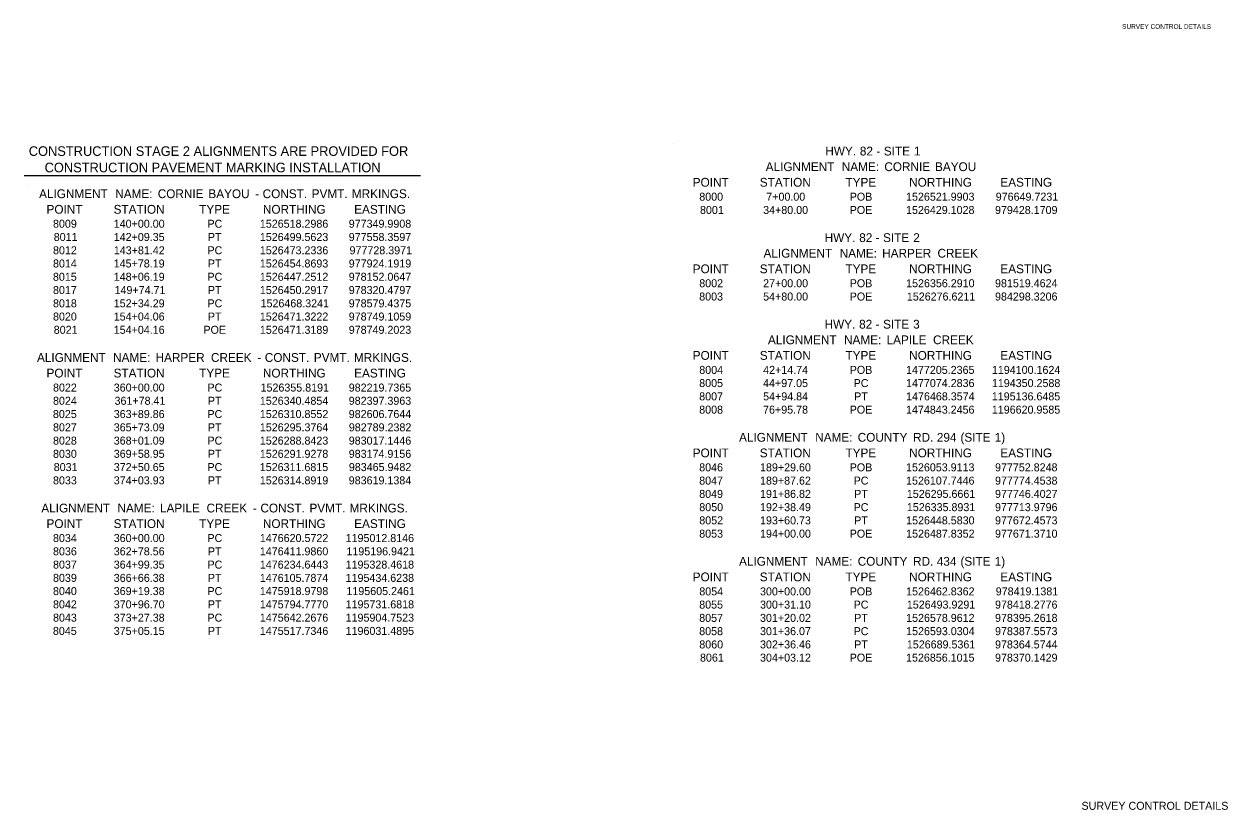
# Model space of a CAD drawing. Extents: x 977669 to 1196358, y 1472413 to 1526490.
# Drawn here: x 1194854 to 1196358, y 1472413 to 1473395 of the extents above; entities that cross this region are included whole.
import ezdxf

# ---------------------------------------------------------------- set-up
doc = ezdxf.new("R2010")
doc.units = 0
for name, color, linetype in [('Default', 7, 'Continuous'), ('R_Annotation', 7, 'Continuous'), ('R_Border', 7, 'Continuous')]:
    doc.layers.add(name, color=color, linetype=linetype)

msp = doc.modelspace()

# ---------------------------------------------------------------- linework, layer by layer
at = {"layer": 'Default'}
msp.add_line((1194853.8, 1473205.4), (1195349.1, 1473205.4), dxfattribs=at)
at = {"layer": 'R_Border'}
for p, q in [((1195666.1, 1473245.9), (1195666.1, 1473245.9)), ((1194858.4, 1473192.6), (1194858.4, 1473192.6))]:
    msp.add_line(p, q, dxfattribs=at)

# ---------------------------------------------------------------- texts
at = {"layer": 'Default'}
for s, height, p in [('CONSTRUCTION STAGE 2 ALIGNMENTS ARE PROVIDED FOR', 12, (1194859.7, 1473230.1)), ('HWY.', 11, (1195855.2, 1473230.6)), (' 82', 11, (1195894.3, 1473230.6)), (' SITE', 11, (1195924.2, 1473230.6)), (' 1', 11, (1195961.8, 1473230.6)), (' -', 11, (1195914.9, 1473230.6)), ('CONSTRUCTION PAVEMENT MARKING INSTALLATION', 12, (1194879.5, 1473209.6)), ('ALIGNMENT', 11, (1195780.7, 1473211.1)), (' NAME:', 11, (1195871.7, 1473211.1)), (' CORNIE', 11, (1195924.9, 1473211.1)), (' BAYOU', 11, (1195988.2, 1473211.1)), ('POINT', 11, (1195689.5, 1473191.6)), ('STATION', 11, (1195773.3, 1473191.6)), ('TYPE', 11, (1195880.4, 1473191.6)), ('NORTHING', 11, (1195960, 1473191.6)), ('EASTING', 11, (1196074, 1473191.6)), ('ALIGNMENT', 11, (1194872.6, 1473177.3)), (' NAME:', 11, (1194963.7, 1473177.3)), (' CORNIE', 11, (1195016.8, 1473177.3)), (' BAYOU', 11, (1195080.1, 1473177.3)), (' -', 11, (1195138.6, 1473177.3)), (' CONST.', 11, (1195147.9, 1473177.3)), (' PVMT.', 11, (1195209.2, 1473177.3)), (' MRKINGS.', 11, (1195259.4, 1473177.3)), ('8000', 10, (1195697.7, 1473174.1)), ('7+00.00', 10, (1195781.4, 1473174.1)), ('POB', 10, (1195885.7, 1473174.1)), ('1526521.9903', 10, (1195956.1, 1473174.1)), ('976649.7231', 10, (1196068.2, 1473174.1)), ('POINT', 11, (1194881.9, 1473157.8)), ('STATION', 11, (1194965.7, 1473157.8)), ('TYPE', 11, (1195072.7, 1473157.8)), ('NORTHING', 11, (1195152.3, 1473157.8)), ('EASTING', 11, (1195266.4, 1473157.8)), ('8001', 10, (1195698.6, 1473157.5)), ('34+80.00', 10, (1195777.5, 1473157.5)), ('POE', 10, (1195885.7, 1473157.5)), ('1526429.1028', 10, (1195956.1, 1473157.5)), ('979428.1709', 10, (1196067.3, 1473157.5)), ('8009', 10, (1194890, 1473140.3)), ('140+00.00', 10, (1194965.9, 1473140.3)), ('PC', 10, (1195083, 1473140.3)), ('1526518.2986', 10, (1195148.5, 1473140.3)), ('977349.9908', 10, (1195259.6, 1473140.3)), ('8011', 10, (1194890.9, 1473123.7)), ('142+09.35', 10, (1194965.9, 1473123.7)), ('PT', 10, (1195083.6, 1473123.7)), ('1526499.5623', 10, (1195148.5, 1473123.7)), ('977558.3597', 10, (1195259.6, 1473123.7)), (' 82', 11, (1195893.5, 1473122.4)), (' SITE', 11, (1195923.3, 1473122.4)), (' 2', 11, (1195961, 1473122.4)), ('HWY.', 11, (1195854.4, 1473122.4)), (' -', 11, (1195914, 1473122.4)), ('8012', 10, (1194890, 1473107.1)), ('143+81.42', 10, (1194966, 1473107.1)), ('PC', 10, (1195083, 1473107.1)), ('1526473.2336', 10, (1195148.5, 1473107.1)), ('977728.3971', 10, (1195260.6, 1473107.1)), ('ALIGNMENT', 11, (1195778, 1473102.9)), (' NAME:', 11, (1195869.1, 1473102.9)), (' HARPER', 11, (1195922.2, 1473102.9)), (' CREEK', 11, (1195991.3, 1473102.9)), ('8014', 10, (1194890, 1473090.6)), ('145+78.19', 10, (1194965.9, 1473090.6)), ('PT', 10, (1195083.6, 1473090.6)), ('1526454.8693', 10, (1195148.5, 1473090.6)), ('977924.1919', 10, (1195259.6, 1473090.6)), ('POINT', 11, (1195689.5, 1473083.4)), ('STATION', 11, (1195773.3, 1473083.4)), ('TYPE', 11, (1195880.4, 1473083.4)), ('NORTHING', 11, (1195960, 1473083.4)), ('EASTING', 11, (1196074, 1473083.4)), ('8015', 10, (1194889.9, 1473074)), ('148+06.19', 10, (1194965.9, 1473074)), ('PC', 10, (1195083, 1473074)), ('1526447.2512', 10, (1195148.5, 1473074)), ('978152.0647', 10, (1195259.6, 1473074)), ('8002', 10, (1195697.7, 1473065.9)), ('27+00.00', 10, (1195777.5, 1473065.9)), ('POB', 10, (1195885.7, 1473065.9)), ('1526356.2910', 10, (1195956.2, 1473065.9)), ('981519.4624', 10, (1196067.3, 1473065.9)), ('8017', 10, (1194890, 1473057.4)), ('149+74.71', 10, (1194966.9, 1473057.4)), ('PT', 10, (1195083.6, 1473057.4)), ('1526450.2917', 10, (1195148.5, 1473057.4)), ('978320.4797', 10, (1195259.6, 1473057.4)), ('8003', 10, (1195697.6, 1473049.3)), ('54+80.00', 10, (1195777.5, 1473049.3)), ('POE', 10, (1195885.7, 1473049.3)), ('1526276.6211', 10, (1195957.1, 1473049.3)), ('984298.3206', 10, (1196067.3, 1473049.3)), ('8018', 10, (1194890, 1473040.8)), ('152+34.29', 10, (1194965.9, 1473040.8)), ('PC', 10, (1195083, 1473040.8)), ('1526468.3241', 10, (1195149.4, 1473040.8)), ('978579.4375', 10, (1195259.6, 1473040.8)), ('8020', 10, (1194890, 1473024.3)), ('154+04.06', 10, (1194965.9, 1473024.3)), ('PT', 10, (1195083.6, 1473024.3)), ('1526471.3222', 10, (1195148.5, 1473024.3)), ('978749.1059', 10, (1195259.6, 1473024.3)), ('8021', 10, (1194890.9, 1473007.7)), ('154+04.16', 10, (1194965.9, 1473007.7)), ('POE', 10, (1195078, 1473007.7)), ('1526471.3189', 10, (1195148.5, 1473007.7)), ('978749.2023', 10, (1195259.6, 1473007.7)), ('HWY.', 11, (1195854.3, 1473014.2)), (' 82', 11, (1195893.4, 1473014.2)), (' -', 11, (1195914, 1473014.2)), (' SITE', 11, (1195923.3, 1473014.2)), (' 3', 11, (1195960.9, 1473014.2)), ('ALIGNMENT', 11, (1195783.5, 1472994.7)), (' NAME:', 11, (1195874.5, 1472994.7)), (' LAPILE', 11, (1195927.7, 1472994.7)), (' CREEK', 11, (1195985.8, 1472994.7)), ('ALIGNMENT', 11, (1194870, 1472972.6)), (' NAME:', 11, (1194961, 1472972.6)), (' HARPER', 11, (1195014.1, 1472972.6)), (' CREEK', 11, (1195083.3, 1472972.6)), (' CONST.', 11, (1195150.6, 1472972.6)), (' PVMT.', 11, (1195211.9, 1472972.6)), (' MRKINGS.', 11, (1195262, 1472972.6)), ('POINT', 11, (1195689.5, 1472975.2)), ('STATION', 11, (1195773.3, 1472975.2)), ('TYPE', 11, (1195880.4, 1472975.2)), ('NORTHING', 11, (1195960, 1472975.2)), ('EASTING', 11, (1196074, 1472975.2)), (' -', 11, (1195141.3, 1472972.6)), ('POINT', 11, (1194881.9, 1472953.1)), ('STATION', 11, (1194965.7, 1472953.1)), ('TYPE', 11, (1195072.7, 1472953.1)), ('NORTHING', 11, (1195152.3, 1472953.1)), ('EASTING', 11, (1195266.4, 1472953.1)), ('8004', 10, (1195697.7, 1472957.6)), ('42+14.74', 10, (1195777.5, 1472957.6)), ('POB', 10, (1195885.7, 1472957.6)), ('1477205.2365', 10, (1195956.1, 1472957.6)), ('1194100.1624', 10, (1196063.4, 1472957.6)), ('8022', 10, (1194890, 1472935.5)), ('360+00.00', 10, (1194965.9, 1472935.5)), ('PC', 10, (1195083, 1472935.5)), ('1526355.8191', 10, (1195149.4, 1472935.5)), ('982219.7365', 10, (1195259.6, 1472935.5)), ('8005', 10, (1195697.6, 1472941.1)), ('44+97.05', 10, (1195777.4, 1472941.1)), ('PC', 10, (1195890.6, 1472941.1)), ('1477074.2836', 10, (1195956.1, 1472941.1)), ('1194350.2588', 10, (1196063.4, 1472941.1)), ('8024', 10, (1194890, 1472919)), ('361+78.41', 10, (1194966.9, 1472919)), ('PT', 10, (1195083.6, 1472919)), ('1526340.4854', 10, (1195148.5, 1472919)), ('982397.3963', 10, (1195259.6, 1472919)), ('8007', 10, (1195697.6, 1472924.5)), ('54+94.84', 10, (1195777.5, 1472924.5)), ('PT', 10, (1195891.3, 1472924.5)), ('1476468.3574', 10, (1195956.2, 1472924.5)), ('1195136.6485', 10, (1196063.3, 1472924.5)), ('8025', 10, (1194889.9, 1472902.4)), ('363+89.86', 10, (1194965.9, 1472902.4)), ('PC', 10, (1195083, 1472902.4)), ('1526310.8552', 10, (1195148.5, 1472902.4)), ('982606.7644', 10, (1195259.6, 1472902.4)), ('8008', 10, (1195697.6, 1472907.9)), ('76+95.78', 10, (1195777.4, 1472907.9)), ('POE', 10, (1195885.7, 1472907.9)), ('1474843.2456', 10, (1195956.1, 1472907.9)), ('1196620.9585', 10, (1196063.3, 1472907.9)), ('8027', 10, (1194890, 1472885.8)), ('365+73.09', 10, (1194965.9, 1472885.8)), ('PT', 10, (1195083.6, 1472885.8)), ('1526295.3764', 10, (1195148.5, 1472885.8)), ('982789.2382', 10, (1195259.7, 1472885.8)), ('8028', 10, (1194890, 1472869.2)), ('368+01.09', 10, (1194965.9, 1472869.2)), ('PC', 10, (1195083, 1472869.2)), ('1526288.8423', 10, (1195148.5, 1472869.2)), ('983017.1446', 10, (1195259.6, 1472869.2)), ('ALIGNMENT', 11, (1195747.4, 1472872.8)), (' NAME:', 11, (1195838.5, 1472872.8)), (' COUNTY', 11, (1195891.6, 1472872.8)), (' RD.', 11, (1195960.8, 1472872.8)), (' 294', 11, (1195990.5, 1472872.8)), (' (SITE', 11, (1196020, 1472872.8)), (' 1)', 11, (1196062.8, 1472872.8)), ('8030', 10, (1194890, 1472852.7)), ('369+58.95', 10, (1194965.9, 1472852.7)), ('1526291.9278', 10, (1195148.5, 1472852.7)), ('983174.9156', 10, (1195259.6, 1472852.7)), ('POINT', 11, (1195689.5, 1472853.3)), ('STATION', 11, (1195773.3, 1472853.3)), ('TYPE', 11, (1195880.4, 1472853.3)), ('NORTHING', 11, (1195960, 1472853.3)), ('EASTING', 11, (1196074, 1472853.3)), ('PT', 10, (1195083.6, 1472852.7)), ('8031', 10, (1194890.9, 1472836.1)), ('372+50.65', 10, (1194965.9, 1472836.1)), ('PC', 10, (1195083, 1472836.1)), ('1526311.6815', 10, (1195148.4, 1472836.1)), ('983465.9482', 10, (1195259.7, 1472836.1)), ('8046', 10, (1195697.6, 1472835.8)), ('189+29.60', 10, (1195773.6, 1472835.8)), ('POB', 10, (1195885.7, 1472835.8)), ('1526053.9113', 10, (1195956.1, 1472835.8)), ('977752.8248', 10, (1196067.3, 1472835.8)), ('8033', 10, (1194890, 1472819.5)), ('374+03.93', 10, (1194965.9, 1472819.5)), ('PT', 10, (1195083.6, 1472819.5)), ('1526314.8919', 10, (1195148.5, 1472819.5)), ('983619.1384', 10, (1195259.6, 1472819.5)), ('8047', 10, (1195697.6, 1472819.2)), ('189+87.62', 10, (1195773.6, 1472819.2)), ('PC', 10, (1195890.6, 1472819.2)), ('1526107.7446', 10, (1195956.1, 1472819.2)), ('977774.4538', 10, (1196067.3, 1472819.2)), ('8049', 10, (1195697.6, 1472802.6)), ('191+86.82', 10, (1195773.6, 1472802.6)), ('PT', 10, (1195891.3, 1472802.6)), ('1526295.6661', 10, (1195957.1, 1472802.6)), ('977746.4027', 10, (1196067.3, 1472802.6)), ('ALIGNMENT', 11, (1194875.4, 1472784.4)), (' NAME:', 11, (1194966.5, 1472784.4)), (' LAPILE', 11, (1195019.6, 1472784.4)), (' CREEK', 11, (1195077.8, 1472784.4)), (' -', 11, (1195135.8, 1472784.4)), (' CONST.', 11, (1195145.1, 1472784.4)), (' PVMT.', 11, (1195206.4, 1472784.4)), (' MRKINGS.', 11, (1195256.6, 1472784.4)), ('8050', 10, (1195697.7, 1472786)), ('192+38.49', 10, (1195773.6, 1472786)), ('PC', 10, (1195890.6, 1472786)), ('1526335.8931', 10, (1195957.1, 1472786)), ('977713.9796', 10, (1196067.3, 1472786)), ('POINT', 11, (1194881.9, 1472764.9)), ('STATION', 11, (1194965.7, 1472764.9)), ('TYPE', 11, (1195072.7, 1472764.9)), ('NORTHING', 11, (1195152.3, 1472764.9)), ('EASTING', 11, (1195266.4, 1472764.9)), ('8052', 10, (1195697.7, 1472769.5)), ('193+60.73', 10, (1195773.6, 1472769.5)), ('PT', 10, (1195891.3, 1472769.5)), ('1526448.5830', 10, (1195956.2, 1472769.5)), ('977672.4573', 10, (1196067.3, 1472769.5)), ('8034', 10, (1194890, 1472747.4)), ('360+00.00', 10, (1194965.9, 1472747.4)), ('PC', 10, (1195083, 1472747.4)), ('1476620.5722', 10, (1195148.5, 1472747.4)), ('1195012.8146', 10, (1195255.7, 1472747.4)), ('8053', 10, (1195697.6, 1472752.9)), ('194+00.00', 10, (1195773.6, 1472752.9)), ('POE', 10, (1195885.7, 1472752.9)), ('1526487.8352', 10, (1195956.2, 1472752.9)), ('977671.3710', 10, (1196067.3, 1472752.9)), ('8036', 10, (1194890, 1472730.8)), ('362+78.56', 10, (1194965.9, 1472730.8)), ('PT', 10, (1195083.6, 1472730.8)), ('1476411.9860', 10, (1195148.5, 1472730.8)), ('1195196.9421', 10, (1195256.7, 1472730.8)), ('ALIGNMENT', 11, (1195747.4, 1472717.8)), (' NAME:', 11, (1195838.5, 1472717.8)), (' COUNTY', 11, (1195891.6, 1472717.8)), (' RD.', 11, (1195960.8, 1472717.8)), (' 434', 11, (1195990.5, 1472717.8)), (' (SITE', 11, (1196020, 1472717.8)), (' 1)', 11, (1196062.8, 1472717.8)), ('8037', 10, (1194890, 1472714.2)), ('364+99.35', 10, (1194965.9, 1472714.2)), ('PC', 10, (1195083, 1472714.2)), ('1476234.6443', 10, (1195148.5, 1472714.2)), ('1195328.4618', 10, (1195255.7, 1472714.2)), ('8039', 10, (1194890, 1472697.6)), ('366+66.38', 10, (1194965.9, 1472697.6)), ('PT', 10, (1195083.6, 1472697.6)), ('1476105.7874', 10, (1195148.5, 1472697.6)), ('1195434.6238', 10, (1195255.7, 1472697.6)), ('POINT', 11, (1195689.5, 1472698.3)), ('STATION', 11, (1195773.3, 1472698.3)), ('TYPE', 11, (1195880.4, 1472698.3)), ('NORTHING', 11, (1195960, 1472698.3)), ('EASTING', 11, (1196074, 1472698.3)), ('8040', 10, (1194890, 1472681.1)), ('369+19.38', 10, (1194965.9, 1472681.1)), ('PC', 10, (1195083, 1472681.1)), ('1475918.9798', 10, (1195148.5, 1472681.1)), ('1195605.2461', 10, (1195256.7, 1472681.1)), ('8054', 10, (1195697.7, 1472680.7)), ('300+00.00', 10, (1195773.6, 1472680.7)), ('POB', 10, (1195885.7, 1472680.7)), ('1526462.8362', 10, (1195956.2, 1472680.7)), ('978419.1381', 10, (1196068.2, 1472680.7)), ('8042', 10, (1194890, 1472664.5)), ('370+96.70', 10, (1194965.9, 1472664.5)), ('PT', 10, (1195083.6, 1472664.5)), ('1475794.7770', 10, (1195148.5, 1472664.5)), ('1195731.6818', 10, (1195255.7, 1472664.5)), ('8055', 10, (1195697.6, 1472664.2)), ('300+31.10', 10, (1195773.6, 1472664.2)), ('PC', 10, (1195890.6, 1472664.2)), ('1526493.9291', 10, (1195957.1, 1472664.2)), ('978418.2776', 10, (1196067.3, 1472664.2)), ('8043', 10, (1194890, 1472647.9)), ('373+27.38', 10, (1194965.9, 1472647.9)), ('PC', 10, (1195083, 1472647.9)), ('1475642.2676', 10, (1195148.5, 1472647.9)), ('1195904.7523', 10, (1195255.7, 1472647.9)), ('8057', 10, (1195697.6, 1472647.6)), ('301+20.02', 10, (1195773.6, 1472647.6)), ('PT', 10, (1195891.3, 1472647.6)), ('1526578.9612', 10, (1195956.2, 1472647.6)), ('978395.2618', 10, (1196067.3, 1472647.6)), ('8045', 10, (1194889.9, 1472631.3)), ('375+05.15', 10, (1194965.9, 1472631.3)), ('PT', 10, (1195083.6, 1472631.3)), ('1475517.7346', 10, (1195148.5, 1472631.3)), ('1196031.4895', 10, (1195255.7, 1472631.3)), ('8058', 10, (1195697.6, 1472631)), ('301+36.07', 10, (1195773.6, 1472631)), ('PC', 10, (1195890.6, 1472631)), ('1526593.0304', 10, (1195956.2, 1472631)), ('978387.5573', 10, (1196067.3, 1472631)), ('8060', 10, (1195697.7, 1472614.4)), ('302+36.46', 10, (1195773.6, 1472614.4)), ('PT', 10, (1195891.3, 1472614.4)), ('1526689.5361', 10, (1195957.1, 1472614.4)), ('978364.5744', 10, (1196067.3, 1472614.4)), ('8061', 10, (1195698.6, 1472597.9)), ('304+03.12', 10, (1195773.6, 1472597.9)), ('POE', 10, (1195885.7, 1472597.9)), ('1526856.1015', 10, (1195956.1, 1472597.9)), ('978370.1429', 10, (1196067.3, 1472597.9))]:
    msp.add_text(s, height=height, dxfattribs=at).set_placement(p)
at = {"layer": 'R_Annotation'}
msp.add_text('SURVEY CONTROL DETAILS', height=10, dxfattribs=at).set_placement((1196175.4, 1472412.7))
at = {"layer": 'R_Border'}
msp.add_text('SURVEY CONTROL DETAILS', height=5.862, dxfattribs=at).set_placement((1196226.1, 1473388.9))

doc.saveas('drawing.dxf')
